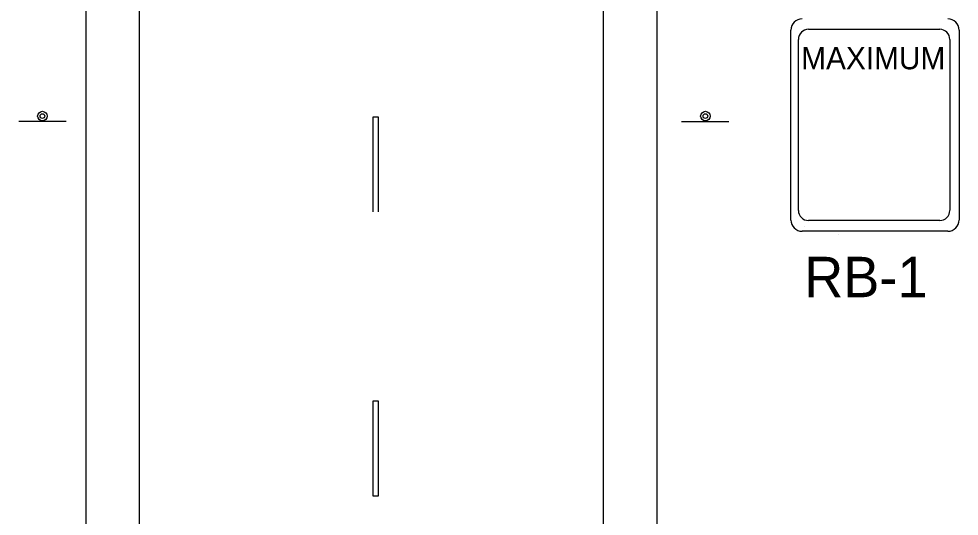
# Model space of a CAD drawing. Extents: x 1314 to 1530, y 165 to 444.
# Drawn here: x 1363.02 to 1411.07, y 345.46 to 370.88 of the extents above; entities that cross this region are included whole.
import ezdxf

# ---------------------------------------------------------------- set-up
doc = ezdxf.new("R2010")
doc.units = 0
for name, color, linetype in [('Level 10', 7, 'Continuous'), ('Level 2', 7, 'Continuous'), ('Level 44', 7, 'Continuous')]:
    doc.layers.add(name, color=color, linetype=linetype)

msp = doc.modelspace()

# ---------------------------------------------------------------- linework, layer by layer
at = {"layer": 'Level 10'}
for p, q in [((1366.452, 414.007), (1366.452, 189.638)), ((1369.178, 414.007), (1369.178, 189.638)), ((1392.884, 414.007), (1392.884, 189.638)), ((1395.628, 414.007), (1395.628, 189.638))]:
    msp.add_line(p, q, dxfattribs=at)
at = {"layer": 'Level 2'}
for p, q in [((1381.108, 365.854), (1381.108, 361.016)), ((1381.398, 365.854), (1381.108, 365.854)), ((1381.398, 361.016), (1381.398, 365.854)), ((1381.108, 351.34), (1381.108, 346.502)), ((1381.398, 351.34), (1381.108, 351.34)), ((1381.398, 346.502), (1381.398, 351.34)), ((1381.108, 346.502), (1381.398, 346.502))]:
    msp.add_line(p, q, dxfattribs=at)
at = {"layer": 'Level 44'}
for p, q in [((1402.476, 360.601), (1402.476, 370.311)), ((1403.376, 370.349), (1410.08, 370.349)), ((1411.074, 370.311), (1411.074, 360.601)), ((1402.859, 361.094), (1402.859, 369.832)), ((1410.597, 369.832), (1410.597, 361.094)), ((1365.438, 365.642), (1363.019, 365.642)), ((1396.889, 365.642), (1399.308, 365.642)), ((1402.859, 361.091), (1402.859, 361.094)), ((1402.476, 360.598), (1402.476, 360.601)), ((1410.08, 360.575), (1403.376, 360.575)), ((1410.498, 360.025), (1403.05, 360.025)), ((1403.182, 360.265), (1403.182, 360.265)), ((1404.93, 359.867), (1404.93, 359.867))]:
    msp.add_line(p, q, dxfattribs=at)
for centre, radius in [((1364.224, 365.913), 0.242), ((1364.224, 365.913), 0.121), ((1398.103, 365.913), 0.242), ((1398.103, 365.913), 0.121)]:
    msp.add_circle(centre, radius, dxfattribs=at)
for centre, radius, start, end in [((1403.051, 370.31), 0.575, 90, 180), ((1410.499, 370.31), 0.575, 360, 90), ((1403.376, 369.83), 0.517, 90, 180), ((1410.079, 369.83), 0.517, 360, 90), ((1403.376, 361.091), 0.517, 180, 270), ((1410.079, 361.091), 0.517, 270, 360), ((1403.051, 360.599), 0.575, 180, 270), ((1410.499, 360.599), 0.575, 270, 360)]:
    msp.add_arc(centre, radius, start, end, dxfattribs=at)

# ---------------------------------------------------------------- texts
at = {"layer": 'Level 10'}
msp.add_text('RB-1', height=2.0682, rotation=360, dxfattribs=at).set_placement((1403.153, 356.65))
at = {"layer": 'Level 44'}
msp.add_text('MAXIMUM', height=1.1394, rotation=360, dxfattribs=at).set_placement((1403, 368.303))

doc.saveas('drawing.dxf')
